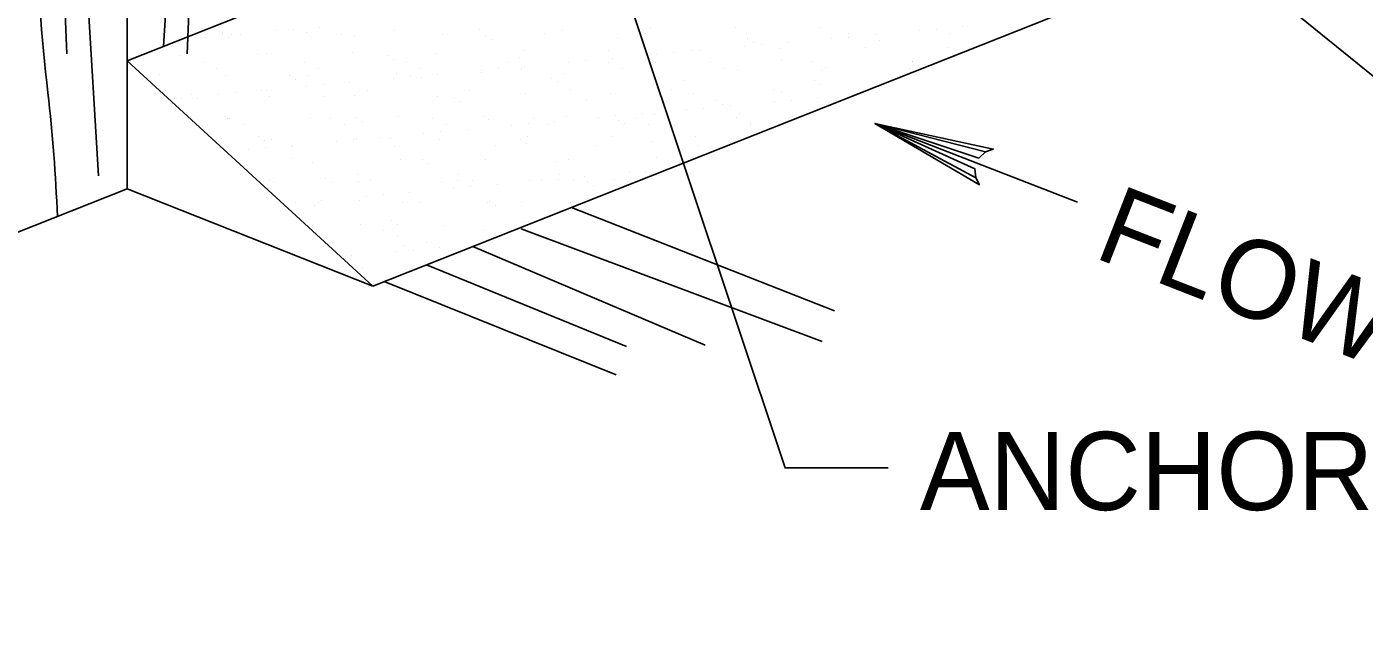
# Model space of a CAD drawing. Extents: x 636462 to 637367, y 299944 to 300538.
# Drawn here: x 636640.4 to 636691.7, y 300035.8 to 300059.3 of the extents above; entities that cross this region are included whole.
import ezdxf

# ---------------------------------------------------------------- set-up
doc = ezdxf.new("R2010")
doc.units = 0
doc.layers.add('Default', color=7, linetype='Continuous')

msp = doc.modelspace()

# ---------------------------------------------------------------- linework, layer by layer
at = {"layer": 'Default'}
for p, q in [((636644.271, 300057.985), (636722.375, 300088.958)), ((636644.271, 300057.268), (636644.271, 300084.96)), ((636653.687, 300049.343), (636731.791, 300080.316)), ((636641.965, 300058.247), (636641.783, 300062.813)), ((636646.577, 300058.247), (636646.759, 300062.813)), ((636642.761, 300060.357), (636643.179, 300053.567)), ((636645.781, 300060.357), (636645.669, 300058.54)), ((636647.935, 300059.032), (636647.935, 300059.032)), ((636647.943, 300059.064), (636647.943, 300059.064)), ((636649.978, 300059.125), (636649.978, 300059.125)), ((636650.627, 300059.183), (636650.627, 300059.183)), ((636651.133, 300059.054), (636651.133, 300059.054)), ((636651.641, 300059.275), (636651.641, 300059.275)), ((636654.501, 300059.137), (636654.501, 300059.137)), ((636656.367, 300059.005), (636656.367, 300059.005)), ((636657.766, 300059.166), (636657.766, 300059.166)), ((636660.25, 300059.01), (636660.25, 300059.01)), ((636660.956, 300059.155), (636660.956, 300059.155)), ((636664.134, 300059.015), (636664.134, 300059.015)), ((636664.324, 300059.238), (636664.324, 300059.238)), ((636667.588, 300059.267), (636667.588, 300059.267)), ((636668.018, 300059.02), (636668.018, 300059.02)), ((636670.779, 300059.257), (636670.779, 300059.257)), ((636671.901, 300059.025), (636671.901, 300059.025)), ((636674.626, 300059.136), (636674.626, 300059.136)), ((636675.275, 300059.194), (636675.275, 300059.194)), ((636675.785, 300059.03), (636675.785, 300059.03)), ((636676.289, 300059.286), (636676.289, 300059.286)), ((636646.621, 300058.821), (636646.621, 300058.821)), ((636647.27, 300058.88), (636647.27, 300058.88)), ((636648.164, 300058.887), (636648.164, 300058.887)), ((636648.284, 300058.972), (636648.284, 300058.972)), ((636648.6, 300058.996), (636648.6, 300058.996)), ((636652.483, 300059.001), (636652.483, 300059.001)), ((636652.998, 300058.956), (636652.998, 300058.956)), ((636657.988, 300058.927), (636657.988, 300058.927)), ((636658.218, 300058.782), (636658.218, 300058.782)), ((636663.052, 300058.851), (636663.052, 300058.851)), ((636667.912, 300058.529), (636667.912, 300058.529)), ((636668.042, 300058.821), (636668.042, 300058.821)), ((636668.272, 300058.677), (636668.272, 300058.677)), ((636668.561, 300058.587), (636668.561, 300058.587)), ((636669.575, 300058.679), (636669.575, 300058.679)), ((636671.269, 300058.832), (636671.269, 300058.832)), ((636671.918, 300058.891), (636671.918, 300058.891)), ((636672.932, 300058.983), (636672.932, 300058.983)), ((636673.106, 300058.746), (636673.106, 300058.746)), ((636644.271, 300057.985), (636653.687, 300049.343)), ((636646.261, 300058.178), (636646.261, 300058.178)), ((636649.249, 300058.204), (636649.249, 300058.204)), ((636649.629, 300058.261), (636649.629, 300058.261)), ((636652.894, 300058.29), (636652.894, 300058.29)), ((636654.24, 300058.175), (636654.24, 300058.175)), ((636654.469, 300058.03), (636654.469, 300058.03)), ((636656.084, 300058.279), (636656.084, 300058.279)), ((636659.303, 300058.099), (636659.303, 300058.099)), ((636659.452, 300058.363), (636659.452, 300058.363)), ((636662.716, 300058.391), (636662.716, 300058.391)), ((636662.861, 300058.072), (636662.861, 300058.072)), ((636664.293, 300058.07), (636664.293, 300058.07)), ((636664.555, 300058.225), (636664.555, 300058.225)), ((636665.204, 300058.284), (636665.204, 300058.284)), ((636665.907, 300058.381), (636665.907, 300058.381)), ((636666.218, 300058.375), (636666.218, 300058.375)), ((636669.275, 300058.464), (636669.275, 300058.464)), ((636669.357, 300057.994), (636669.357, 300057.994)), ((636672.539, 300058.493), (636672.539, 300058.493)), ((636675.729, 300058.482), (636675.729, 300058.482)), ((636647.188, 300057.909), (636647.188, 300057.909)), ((636647.714, 300057.679), (636647.714, 300057.679)), ((636651.071, 300057.914), (636651.071, 300057.914)), ((636651.597, 300057.684), (636651.597, 300057.684)), ((636654.58, 300057.487), (636654.58, 300057.487)), ((636654.955, 300057.919), (636654.955, 300057.919)), ((636655.481, 300057.689), (636655.481, 300057.689)), ((636657.841, 300057.618), (636657.841, 300057.618)), ((636657.844, 300057.515), (636657.844, 300057.515)), ((636658.49, 300057.677), (636658.49, 300057.677)), ((636658.839, 300057.924), (636658.839, 300057.924)), ((636659.364, 300057.694), (636659.364, 300057.694)), ((636659.504, 300057.768), (636659.504, 300057.768)), ((636661.034, 300057.505), (636661.034, 300057.505)), ((636661.198, 300057.922), (636661.198, 300057.922)), ((636661.847, 300057.98), (636661.847, 300057.98)), ((636662.722, 300057.929), (636662.722, 300057.929)), ((636663.248, 300057.699), (636663.248, 300057.699)), ((636664.403, 300057.588), (636664.403, 300057.588)), ((636664.523, 300057.925), (636664.523, 300057.925)), ((636666.606, 300057.934), (636666.606, 300057.934)), ((636667.132, 300057.703), (636667.132, 300057.703)), ((636667.667, 300057.617), (636667.667, 300057.617)), ((636670.489, 300057.938), (636670.489, 300057.938)), ((636670.857, 300057.606), (636670.857, 300057.606)), ((636671.015, 300057.708), (636671.015, 300057.708)), ((636674.225, 300057.689), (636674.225, 300057.689)), ((636674.347, 300057.964), (636674.347, 300057.964)), ((636674.373, 300057.943), (636674.373, 300057.943)), ((636674.577, 300057.82), (636674.577, 300057.82)), ((636644.271, 300057.268), (636644.271, 300053.077)), ((636645.501, 300057.452), (636645.501, 300057.452)), ((636648.022, 300057.414), (636648.022, 300057.414)), ((636650.491, 300057.423), (636650.491, 300057.423)), ((636650.72, 300057.278), (636650.72, 300057.278)), ((636651.128, 300057.011), (636651.128, 300057.011)), ((636651.212, 300057.403), (636651.212, 300057.403)), ((636651.777, 300057.07), (636651.777, 300057.07)), ((636652.791, 300057.161), (636652.791, 300057.161)), ((636654.484, 300057.314), (636654.484, 300057.314)), ((636655.134, 300057.373), (636655.134, 300057.373)), ((636655.554, 300057.347), (636655.554, 300057.347)), ((636656.147, 300057.465), (636656.147, 300057.465)), ((636660.544, 300057.318), (636660.544, 300057.318)), ((636660.774, 300057.173), (636660.774, 300057.173)), ((636665.608, 300057.242), (636665.608, 300057.242)), ((636670.598, 300057.213), (636670.598, 300057.213)), ((636670.828, 300057.068), (636670.828, 300057.068)), ((636645.723, 300056.846), (636645.723, 300056.846)), ((636646.077, 300056.554), (636646.077, 300056.554)), ((636646.34, 300056.527), (636646.34, 300056.527)), ((636646.742, 300056.671), (636646.742, 300056.671)), ((636646.972, 300056.527), (636646.972, 300056.527)), ((636647.771, 300056.707), (636647.771, 300056.707)), ((636648.42, 300056.766), (636648.42, 300056.766)), ((636649.434, 300056.858), (636649.434, 300056.858)), ((636649.607, 300056.851), (636649.607, 300056.851)), ((636649.708, 300056.611), (636649.708, 300056.611)), ((636651.805, 300056.595), (636651.805, 300056.595)), ((636652.972, 300056.639), (636652.972, 300056.639)), ((636653.49, 300056.856), (636653.49, 300056.856)), ((636656.162, 300056.629), (636656.162, 300056.629)), ((636656.796, 300056.566), (636656.796, 300056.566)), ((636657.374, 300056.86), (636657.374, 300056.86)), ((636659.531, 300056.712), (636659.531, 300056.712)), ((636661.258, 300056.865), (636661.258, 300056.865)), ((636661.859, 300056.49), (636661.859, 300056.49)), ((636662.795, 300056.741), (636662.795, 300056.741)), ((636665.141, 300056.87), (636665.141, 300056.87)), ((636665.985, 300056.73), (636665.985, 300056.73)), ((636666.849, 300056.461), (636666.849, 300056.461)), ((636669.025, 300056.875), (636669.025, 300056.875)), ((636669.353, 300056.813), (636669.353, 300056.813)), ((636669.711, 300056.473), (636669.711, 300056.473)), ((636670.725, 300056.565), (636670.725, 300056.565)), ((636657.025, 300056.421), (636657.025, 300056.421)), ((636664.011, 300055.958), (636664.011, 300055.958)), ((636664.481, 300055.938), (636664.481, 300055.938)), ((636665.705, 300056.111), (636665.705, 300056.111)), ((636666.354, 300056.17), (636666.354, 300056.17)), ((636667.079, 300056.316), (636667.079, 300056.316)), ((636667.368, 300056.262), (636667.368, 300056.262)), ((636667.746, 300055.966), (636667.746, 300055.966)), ((636669.062, 300056.415), (636669.062, 300056.415)), ((636648.057, 300055.844), (636648.057, 300055.844)), ((636648.1, 300055.763), (636648.1, 300055.763)), ((636648.195, 300055.764), (636648.195, 300055.764)), ((636648.721, 300055.534), (636648.721, 300055.534)), ((636651.29, 300055.753), (636651.29, 300055.753)), ((636652.079, 300055.769), (636652.079, 300055.769)), ((636652.604, 300055.539), (636652.604, 300055.539)), ((636653.047, 300055.814), (636653.047, 300055.814)), ((636653.277, 300055.67), (636653.277, 300055.67)), ((636654.659, 300055.836), (636654.659, 300055.836)), ((636655.962, 300055.774), (636655.962, 300055.774)), ((636656.488, 300055.544), (636656.488, 300055.544)), ((636657.923, 300055.865), (636657.923, 300055.865)), ((636658.11, 300055.739), (636658.11, 300055.739)), ((636658.991, 300055.504), (636658.991, 300055.504)), ((636659.64, 300055.563), (636659.64, 300055.563)), ((636659.846, 300055.779), (636659.846, 300055.779)), ((636660.372, 300055.549), (636660.372, 300055.549)), ((636660.654, 300055.655), (636660.654, 300055.655)), ((636661.113, 300055.854), (636661.113, 300055.854)), ((636662.348, 300055.808), (636662.348, 300055.808)), ((636662.997, 300055.866), (636662.997, 300055.866)), ((636663.1, 300055.709), (636663.1, 300055.709)), ((636663.33, 300055.564), (636663.33, 300055.564)), ((636663.729, 300055.784), (636663.729, 300055.784)), ((636664.255, 300055.554), (636664.255, 300055.554)), ((636667.613, 300055.789), (636667.613, 300055.789)), ((636668.139, 300055.558), (636668.139, 300055.558)), ((636668.164, 300055.633), (636668.164, 300055.633)), ((636649.298, 300055.062), (636649.298, 300055.062)), ((636649.528, 300054.918), (636649.528, 300054.918)), ((636649.786, 300054.96), (636649.786, 300054.96)), ((636652.927, 300054.956), (636652.927, 300054.956)), ((636653.051, 300054.989), (636653.051, 300054.989)), ((636653.94, 300055.047), (636653.94, 300055.047)), ((636654.361, 300054.987), (636654.361, 300054.987)), ((636655.634, 300055.201), (636655.634, 300055.201)), ((636656.241, 300054.978), (636656.241, 300054.978)), ((636656.283, 300055.259), (636656.283, 300055.259)), ((636657.297, 300055.351), (636657.297, 300055.351)), ((636659.352, 300054.957), (636659.352, 300054.957)), ((636659.609, 300055.062), (636659.609, 300055.062)), ((636662.873, 300055.09), (636662.873, 300055.09)), ((636666.064, 300055.08), (636666.064, 300055.08)), ((636648.921, 300054.593), (636648.921, 300054.593)), ((636649.57, 300054.652), (636649.57, 300054.652)), ((636650.584, 300054.744), (636650.584, 300054.744)), ((636650.614, 300054.706), (636650.614, 300054.706)), ((636652.277, 300054.897), (636652.277, 300054.897)), ((636654.498, 300054.711), (636654.498, 300054.711)), ((636658.381, 300054.716), (636658.381, 300054.716)), ((636659.581, 300054.813), (636659.581, 300054.813)), ((636662.265, 300054.72), (636662.265, 300054.72)), ((636664.415, 300054.882), (636664.415, 300054.882)), ((636666.148, 300054.725), (636666.148, 300054.725)), ((636650.613, 300054.235), (636650.613, 300054.235)), ((636651.369, 300054.102), (636651.369, 300054.102)), ((636654.737, 300054.186), (636654.737, 300054.186)), ((636655.603, 300054.205), (636655.603, 300054.205)), ((636655.833, 300054.061), (636655.833, 300054.061)), ((636658.001, 300054.214), (636658.001, 300054.214)), ((636660.666, 300054.13), (636660.666, 300054.13)), ((636661.192, 300054.204), (636661.192, 300054.204)), ((636664.56, 300054.287), (636664.56, 300054.287)), ((636665.657, 300054.1), (636665.657, 300054.1)), ((636649.202, 300053.619), (636649.202, 300053.619)), ((636649.728, 300053.389), (636649.728, 300053.389)), ((636651.854, 300053.454), (636651.854, 300053.454)), ((636653.086, 300053.624), (636653.086, 300053.624)), ((636653.612, 300053.394), (636653.612, 300053.394)), ((636656.918, 300053.378), (636656.918, 300053.378)), ((636656.969, 300053.629), (636656.969, 300053.629)), ((636657.495, 300053.399), (636657.495, 300053.399)), ((636659.688, 300053.411), (636659.688, 300053.411)), ((636660.141, 300053.39), (636660.141, 300053.39)), ((636660.79, 300053.449), (636660.79, 300053.449)), ((636660.853, 300053.634), (636660.853, 300053.634)), ((636661.379, 300053.404), (636661.379, 300053.404)), ((636661.804, 300053.541), (636661.804, 300053.541)), ((636662.952, 300053.44), (636662.952, 300053.44)), ((636663.498, 300053.694), (636663.498, 300053.694)), ((636664.147, 300053.753), (636664.147, 300053.753)), ((636600.63, 300035.771), (636644.271, 300053.077)), ((636644.271, 300053.077), (636653.687, 300049.343)), ((636649.865, 300053.31), (636649.865, 300053.31)), ((636652.084, 300053.309), (636652.084, 300053.309)), ((636653.129, 300053.338), (636653.129, 300053.338)), ((636655.09, 300052.934), (636655.09, 300052.934)), ((636656.319, 300053.328), (636656.319, 300053.328)), ((636656.784, 300053.087), (636656.784, 300053.087)), ((636657.433, 300053.145), (636657.433, 300053.145)), ((636658.447, 300053.237), (636658.447, 300053.237)), ((636661.908, 300053.348), (636661.908, 300053.348)), ((636662.138, 300053.204), (636662.138, 300053.204)), ((636650.719, 300052.538), (636650.719, 300052.538)), ((636651.447, 300052.452), (636651.447, 300052.452)), ((636651.621, 300052.561), (636651.621, 300052.561)), ((636651.733, 300052.63), (636651.733, 300052.63)), ((636653.169, 300052.626), (636653.169, 300052.626)), ((636653.427, 300052.783), (636653.427, 300052.783)), ((636654.076, 300052.842), (636654.076, 300052.842)), ((636654.816, 300052.535), (636654.816, 300052.535)), ((636655.505, 300052.566), (636655.505, 300052.566)), ((636658.08, 300052.564), (636658.08, 300052.564)), ((636658.159, 300052.597), (636658.159, 300052.597)), ((636658.389, 300052.452), (636658.389, 300052.452)), ((636659.388, 300052.571), (636659.388, 300052.571)), ((636661.27, 300052.553), (636661.27, 300052.553)), ((636661.296, 300052.361), (636671.37, 300048.401)), ((636654.41, 300051.845), (636654.41, 300051.845)), ((636653.208, 300051.688), (636653.208, 300051.688)), ((636654.093, 300051.479), (636654.093, 300051.479)), ((636654.64, 300051.7), (636654.64, 300051.7)), ((636656.398, 300051.677), (636656.398, 300051.677)), ((636657.976, 300051.484), (636657.976, 300051.484)), ((636659.371, 300051.536), (636670.893, 300047.223)), ((636659.474, 300051.769), (636659.474, 300051.769)), ((636659.766, 300051.761), (636659.766, 300051.761)), ((636654.619, 300051.249), (636654.619, 300051.249)), ((636654.894, 300050.885), (636654.894, 300050.885)), ((636655.725, 300051.017), (636655.725, 300051.017)), ((636656.24, 300050.82), (636656.24, 300050.82)), ((636657.516, 300050.862), (636666.419, 300047.085)), ((636658.502, 300051.254), (636658.502, 300051.254)), ((636652.628, 300050.416), (636652.628, 300050.416)), ((636652.883, 300050.516), (636652.883, 300050.516)), ((636654.577, 300050.669), (636654.577, 300050.669)), ((636655.226, 300050.728), (636655.226, 300050.728)), ((636653.286, 300050.037), (636653.286, 300050.037)), ((636655.736, 300050.156), (636663.407, 300047.034)), ((636654.124, 300049.516), (636663, 300045.947))]:
    msp.add_line(p, q, dxfattribs=at)
for points in [[(636650.484, 300099.295), (636669.477, 300042.377), (636673.427, 300042.377)], [(636698.846, 300055.122), (636694.817, 300055.122), (636674.49, 300071.591)], [(636672.918, 300055.584), (636680.675, 300052.56)], [(636676.78, 300053.491), (636676.744, 300053.844), (636672.918, 300055.584), (636676.78, 300053.491), (636676.919, 300053.231), (636672.918, 300055.584), (636676.9, 300054.254), (636677.156, 300054.489), (636672.918, 300055.584), (636677.452, 300054.598), (636677.156, 300054.489)]]:
    msp.add_lwpolyline(points, dxfattribs=at)
for centre, major_axis, start_param in [((636834.803, 300067.074), (-194.148, 0), 0.028842), ((636505.375, 300049.505), (136.272, 0), 0.026838)]:
    msp.add_ellipse(centre, major_axis=major_axis, ratio=0.686868, start_param=start_param, end_param=0.077486, dxfattribs=at)

# ---------------------------------------------------------------- texts
msp.add_text('FLOW', height=2.998, rotation=338.6988, dxfattribs=at).set_placement((636681.242, 300050.466))
msp.add_text('ANCHORING POSTS', height=2.99804, dxfattribs=at).set_placement((636674.642, 300040.76))

doc.saveas('drawing.dxf')
